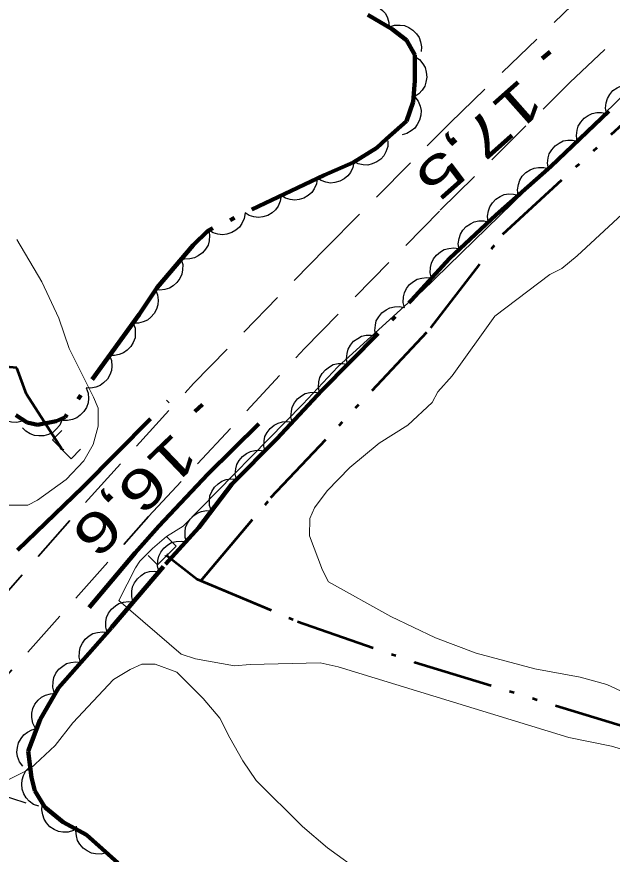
# Model space of a CAD drawing. Extents: x 386081 to 389416, y 5130568 to 5134082.
# Drawn here: x 387889.6 to 387934.2, y 5132287.6 to 5132350.3 of the extents above; entities that cross this region are included whole.
import ezdxf

# ---------------------------------------------------------------- set-up
doc = ezdxf.new("R2010")
doc.units = 0
doc.header["$LTSCALE"] = 1.2
for name, pattern in [('DASH_DOUBLE_DOT', [9.2, 5, -1.2, 0.3, -1.2, 0.3, -1.2]), ('DOT_DASHED', [7.7, 5, -1.2, 0.3, -1.2]), ('LONG_DASHED', [7.5, 6, -1.5]), ('MEDIUM_DASHED', [4.5, 3, -1.5])]:
    doc.linetypes.add(name, pattern=pattern)
for name, color, linetype, lineweight in [('2', 7, 'Continuous', 13), ('21', 7, 'LONG_DASHED', 35), ('26', 7, 'Continuous', 35), ('3', 7, 'Continuous', 140), ('4', 7, 'DASH_DOUBLE_DOT', 53), ('41', 7, 'DOT_DASHED', 25), ('44', 7, 'Continuous', 25)]:
    doc.layers.add(name, color=color, linetype=linetype, lineweight=lineweight)

msp = doc.modelspace()

# ---------------------------------------------------------------- linework, layer by layer
at = {"layer": '2'}
for points in [[(387940.27, 5132349.55), (387919.93, 5132329.72), (387918.88, 5132328.86), (387913.6, 5132324.05), (387910.99, 5132321.25), (387902.03, 5132312.13), (387900.78, 5132311.34), (387899.72, 5132310.46), (387898.77, 5132309.51), (387898.45, 5132309.01), (387897.22, 5132306.55), (387901.87, 5132302.54), (387902.94, 5132302.2), (387905.86, 5132301.67), (387907.04, 5132301.76), (387912.28, 5132301.88), (387913.63, 5132301.59), (387930.91, 5132296.29), (387934.1, 5132295.66), (387937.25, 5132294.71)], [(387887.86, 5132313.7), (387890.4, 5132313.69), (387891.11, 5132314.07), (387893.27, 5132315.62), (387894.6, 5132317.01), (387895.29, 5132318.23), (387895.67, 5132319.61), (387895.66, 5132320.97), (387895.32, 5132321.79), (387893.48, 5132325.44), (387892.71, 5132327.71), (387891.45, 5132330.42), (387889.56, 5132333.59)], [(387940, 5132297.37), (387933.76, 5132300.26), (387931.75, 5132300.82), (387928.36, 5132301.44), (387923.97, 5132302.62), (387920.93, 5132303.75), (387917.58, 5132305.37), (387912.9, 5132307.96), (387912.45, 5132308.82), (387911.48, 5132311.4), (387911.5, 5132312.7), (387911.86, 5132313.5), (387912.8, 5132314.76), (387914.5, 5132316.51), (387916.69, 5132318.33), (387918.84, 5132319.7), (387920.66, 5132321.38), (387921.1, 5132322.19), (387922.17, 5132323.38), (387925.36, 5132327.84)], [(387880.43, 5132289.92), (387882.86, 5132290.75), (387884.73, 5132291.27), (387886.72, 5132292.04), (387890.58, 5132293.94), (387892.45, 5132295.7), (387893.76, 5132297.39), (387896.81, 5132300.64), (387898.06, 5132301.4), (387898.93, 5132301.78), (387899.92, 5132301.79), (387901.54, 5132301.19)]]:
    msp.add_lwpolyline(points, dxfattribs=at)
at = {"layer": '2', "linetype": 'LONG_DASHED'}
for points in [[(387925.36, 5132327.84), (387929.48, 5132330.96), (387930.37, 5132331.43), (387931.52, 5132332.38), (387935.89, 5132336.43)], [(387901.54, 5132301.19), (387903.53, 5132299.23), (387904.77, 5132297.75), (387905.51, 5132296.27), (387906.5, 5132294.54), (387907.5, 5132293.07), (387910.97, 5132289.63), (387912.83, 5132288.04), (387919.29, 5132283.39)]]:
    msp.add_lwpolyline(points, dxfattribs=at)
at = {"layer": '21', "linetype": 'MEDIUM_DASHED'}
for points in [[(387860.78, 5132286.44), (387862.78, 5132287.28), (387865.84, 5132288.2), (387868.86, 5132289.23), (387870.95, 5132290.29), (387873.09, 5132291.74), (387875.38, 5132293.66), (387881.62, 5132300.01), (387887.6, 5132305.78), (387894.9, 5132314.12), (387902.8, 5132322.8), (387912.7, 5132332.94), (387922.03, 5132342.34), (387944.62, 5132364.16), (387960.02, 5132379.36), (387967.89, 5132387.55), (387974.37, 5132394.99), (387979.87, 5132401.66), (387990.47, 5132414.87), (387993.62, 5132418.08), (388000.82, 5132427.01), (388006.82, 5132435.09), (388017.51, 5132449)], [(387871.99, 5132283.29), (387872.81, 5132284.42), (387877.34, 5132288.8), (387880.16, 5132291.8), (387883.3, 5132295.45), (387886.81, 5132298.67), (387899.44, 5132312.84), (387911.12, 5132325.44), (387921.28, 5132335.78), (387930.99, 5132345.34), (387944.01, 5132357.8), (387957.3, 5132370.29), (387966.89, 5132380.09), (387975.16, 5132389.32), (387982.37, 5132397.55), (387987.94, 5132404.97), (387994.4, 5132413.8), (388000.29, 5132420), (388012.45, 5132436.38), (388020.46, 5132446.74)]]:
    msp.add_lwpolyline(points, dxfattribs=at)
at = {"layer": '21', "lineweight": 140}
for points in [[(387889.61, 5132310.34), (387894.52, 5132315.05), (387900.91, 5132321.49)], [(387907.68, 5132319.79), (387903.88, 5132316.01), (387900.21, 5132312.12), (387898.43, 5132310.13), (387894.99, 5132306.03)]]:
    msp.add_lwpolyline(points, dxfattribs=at)
at = {"layer": '26'}
for p, q in [((387892.24, 5132318.58), (387892.94, 5132319.28)), ((387893.64, 5132317.18), (387892.24, 5132318.58)), ((387892.87, 5132317.95), (387892.94, 5132318.02)), ((387893.01, 5132317.81), (387892.87, 5132317.95)), ((387893.01, 5132317.81), (387893.08, 5132317.88)), ((387893.64, 5132317.18), (387894.34, 5132317.88)), ((387901.5, 5132310.62), (387900.8, 5132311.32)), ((387901.5, 5132310.62), (387900.1, 5132309.22)), ((387900.1, 5132309.22), (387899.4, 5132309.92)), ((387900.73, 5132309.85), (387900.66, 5132309.92)), ((387900.87, 5132309.99), (387900.73, 5132309.85)), ((387900.87, 5132309.99), (387900.8, 5132310.06))]:
    msp.add_line(p, q, dxfattribs=at)
at = {"layer": '3'}
for p, q in [((387929.5, 5132347.66), (387928.9, 5132347.14)), ((387903.48, 5132321.24), (387902.9, 5132320.7))]:
    msp.add_line(p, q, dxfattribs=at)
at = {"layer": '4'}
for points in [[(387903.36, 5132308.04), (387908.6, 5132314.26), (387920.58, 5132326.98), (387925.96, 5132333.99), (387955.31, 5132360.98), (387968.85, 5132373.63), (387980.92, 5132386.88), (387997.63, 5132406.11), (388003.3, 5132412.46), (388006.68, 5132415.63), (388007.94, 5132417.55), (388009.44, 5132419.16), (388010.05, 5132419.23), (388010.81, 5132419.74), (388011.93, 5132420.94), (388013.08, 5132422.61), (388014.26, 5132424.98), (388016.25, 5132428.18), (388017.26, 5132429.13), (388018.5, 5132429.83), (388020.36, 5132432)], [(387892.94, 5132317.88), (387890.3, 5132322.01), (387889.56, 5132323.99), (387883.42, 5132324.53), (387868.69, 5132324.8), (387854.75, 5132324.8), (387843.78, 5132324.98), (387834.49, 5132324.37), (387825.45, 5132322.4), (387815.47, 5132320.9), (387809.16, 5132320.4), (387801.96, 5132320.97), (387796.86, 5132320.98), (387791.59, 5132322.3), (387785.98, 5132323.55), (387774.67, 5132327.23), (387758.88, 5132331.38)], [(387900.8, 5132309.92), (387903.08, 5132308.16), (387910.59, 5132304.99), (387919.35, 5132301.95), (387939.96, 5132295.61), (387941.2, 5132294.34), (387941.56, 5132292.55), (387938.27, 5132281.68), (387937.1, 5132271.81), (387937.03, 5132266.91), (387937.28, 5132262.82), (387937.15, 5132259.34), (387936.71, 5132255.8), (387935.77, 5132251.89), (387934.71, 5132248.09), (387931.98, 5132243.59), (387930.17, 5132241.03), (387926.32, 5132237.16)]]:
    msp.add_lwpolyline(points, dxfattribs=at)
at = {"layer": '41'}
msp.add_lwpolyline([(387890.27, 5132291.38), (387887.33, 5132292.33), (387886.21, 5132292.69), (387884.02, 5132293.9)], dxfattribs=at)
at = {"layer": '44'}
for points in [[(387914.87, 5132351.01), (387915.24, 5132351.19), (387915.65, 5132351.25), (387915.98, 5132351.25), (387916.32, 5132351.15), (387916.65, 5132350.99), (387916.94, 5132350.75), (387917.17, 5132350.51), (387917.32, 5132350.2), (387917.43, 5132349.84), (387917.45, 5132349.48)], [(387917.47, 5132349.51), (387917.86, 5132349.64), (387918.27, 5132349.65), (387918.6, 5132349.61), (387918.92, 5132349.48), (387919.23, 5132349.28), (387919.49, 5132348.99), (387919.69, 5132348.73), (387919.8, 5132348.4), (387919.86, 5132348.03), (387919.84, 5132347.68)], [(387919.37, 5132347.3), (387919.72, 5132347.07), (387919.97, 5132346.75), (387920.14, 5132346.47), (387920.23, 5132346.13), (387920.27, 5132345.76), (387920.2, 5132345.38), (387920.11, 5132345.07), (387919.92, 5132344.78), (387919.67, 5132344.5), (387919.37, 5132344.3)], [(387933.72, 5132343.03), (387933.65, 5132343.44), (387933.7, 5132343.84), (387933.79, 5132344.16), (387933.97, 5132344.46), (387934.21, 5132344.74), (387934.53, 5132344.95), (387934.82, 5132345.1), (387935.17, 5132345.17), (387935.54, 5132345.17), (387935.89, 5132345.1)], [(387919.37, 5132344.29), (387919.62, 5132343.96), (387919.77, 5132343.58), (387919.84, 5132343.25), (387919.82, 5132342.9), (387919.73, 5132342.54), (387919.56, 5132342.2), (387919.37, 5132341.93), (387919.1, 5132341.72), (387918.77, 5132341.54), (387918.43, 5132341.44)], [(387931.54, 5132340.96), (387931.47, 5132341.37), (387931.53, 5132341.77), (387931.61, 5132342.09), (387931.8, 5132342.39), (387932.04, 5132342.67), (387932.36, 5132342.88), (387932.65, 5132343.04), (387932.99, 5132343.1), (387933.36, 5132343.1), (387933.72, 5132343.03)], [(387917.36, 5132340.97), (387917.35, 5132340.55), (387917.21, 5132340.17), (387917.06, 5132339.87), (387916.82, 5132339.62), (387916.52, 5132339.4), (387916.17, 5132339.26), (387915.85, 5132339.17), (387915.5, 5132339.18), (387915.14, 5132339.25), (387914.81, 5132339.4)], [(387929.37, 5132338.89), (387929.3, 5132339.3), (387929.35, 5132339.7), (387929.44, 5132340.02), (387929.62, 5132340.32), (387929.87, 5132340.6), (387930.19, 5132340.81), (387930.47, 5132340.97), (387930.82, 5132341.03), (387931.19, 5132341.03), (387931.54, 5132340.96)], [(387914.81, 5132339.39), (387914.74, 5132338.98), (387914.55, 5132338.62), (387914.36, 5132338.35), (387914.08, 5132338.13), (387913.76, 5132337.95), (387913.39, 5132337.86), (387913.06, 5132337.81), (387912.72, 5132337.88), (387912.37, 5132338), (387912.06, 5132338.19)], [(387927.12, 5132336.91), (387927.06, 5132337.32), (387927.13, 5132337.72), (387927.23, 5132338.04), (387927.42, 5132338.33), (387927.68, 5132338.6), (387928, 5132338.8), (387928.3, 5132338.94), (387928.64, 5132338.99), (387929.02, 5132338.99), (387929.36, 5132338.9)], [(387912.07, 5132338.17), (387912.01, 5132337.76), (387911.84, 5132337.39), (387911.66, 5132337.11), (387911.39, 5132336.89), (387911.07, 5132336.7), (387910.7, 5132336.59), (387910.38, 5132336.54), (387910.03, 5132336.58), (387909.68, 5132336.69), (387909.37, 5132336.88)], [(387909.37, 5132336.88), (387909.3, 5132336.46), (387909.13, 5132336.1), (387908.95, 5132335.82), (387908.68, 5132335.59), (387908.36, 5132335.4), (387908, 5132335.3), (387907.67, 5132335.24), (387907.32, 5132335.29), (387906.97, 5132335.4), (387906.66, 5132335.58)], [(387924.87, 5132334.92), (387924.82, 5132335.33), (387924.88, 5132335.73), (387924.98, 5132336.05), (387925.18, 5132336.34), (387925.43, 5132336.61), (387925.76, 5132336.81), (387926.05, 5132336.96), (387926.4, 5132337.01), (387926.77, 5132337), (387927.12, 5132336.91)], [(387906.66, 5132335.58), (387906.6, 5132335.17), (387906.42, 5132334.8), (387906.24, 5132334.52), (387905.98, 5132334.3), (387905.66, 5132334.11), (387905.29, 5132334), (387904.97, 5132333.95), (387904.62, 5132333.99), (387904.26, 5132334.1), (387903.95, 5132334.29)], [(387922.7, 5132332.85), (387922.63, 5132333.26), (387922.69, 5132333.67), (387922.78, 5132333.99), (387922.96, 5132334.28), (387923.21, 5132334.56), (387923.53, 5132334.77), (387923.82, 5132334.92), (387924.16, 5132334.98), (387924.54, 5132334.98), (387924.89, 5132334.9)], [(387903.94, 5132334.31), (387904.01, 5132333.9), (387903.97, 5132333.49), (387903.89, 5132333.17), (387903.71, 5132332.87), (387903.47, 5132332.59), (387903.15, 5132332.37), (387902.87, 5132332.21), (387902.52, 5132332.15), (387902.15, 5132332.13), (387901.8, 5132332.21)], [(387920.62, 5132330.69), (387920.52, 5132331.1), (387920.55, 5132331.5), (387920.61, 5132331.83), (387920.77, 5132332.14), (387921, 5132332.43), (387921.3, 5132332.67), (387921.58, 5132332.84), (387921.92, 5132332.93), (387922.29, 5132332.96), (387922.64, 5132332.91)], [(387901.88, 5132332.13), (387901.99, 5132331.72), (387901.98, 5132331.32), (387901.93, 5132330.99), (387901.78, 5132330.67), (387901.56, 5132330.37), (387901.27, 5132330.13), (387901, 5132329.95), (387900.66, 5132329.85), (387900.29, 5132329.81), (387899.93, 5132329.85)], [(387918.6, 5132328.48), (387918.5, 5132328.88), (387918.52, 5132329.29), (387918.59, 5132329.61), (387918.75, 5132329.92), (387918.97, 5132330.22), (387919.28, 5132330.45), (387919.55, 5132330.63), (387919.89, 5132330.71), (387920.26, 5132330.74), (387920.62, 5132330.69)], [(387899.95, 5132329.83), (387900.11, 5132329.45), (387900.15, 5132329.04), (387900.14, 5132328.71), (387900.03, 5132328.38), (387899.86, 5132328.05), (387899.6, 5132327.77), (387899.35, 5132327.56), (387899.03, 5132327.42), (387898.67, 5132327.33), (387898.31, 5132327.32)], [(387916.46, 5132326.37), (387916.38, 5132326.78), (387916.42, 5132327.19), (387916.49, 5132327.51), (387916.67, 5132327.81), (387916.91, 5132328.09), (387917.22, 5132328.32), (387917.5, 5132328.48), (387917.85, 5132328.55), (387918.22, 5132328.57), (387918.57, 5132328.5)], [(387898.28, 5132327.34), (387898.42, 5132326.95), (387898.44, 5132326.55), (387898.42, 5132326.22), (387898.29, 5132325.89), (387898.1, 5132325.57), (387897.83, 5132325.3), (387897.57, 5132325.1), (387897.24, 5132324.97), (387896.88, 5132324.9), (387896.52, 5132324.91)], [(387914.34, 5132324.24), (387914.26, 5132324.65), (387914.3, 5132325.06), (387914.38, 5132325.38), (387914.56, 5132325.68), (387914.79, 5132325.97), (387915.1, 5132326.19), (387915.39, 5132326.35), (387915.73, 5132326.42), (387916.1, 5132326.44), (387916.46, 5132326.37)], [(387896.52, 5132324.91), (387896.66, 5132324.52), (387896.69, 5132324.11), (387896.66, 5132323.78), (387896.54, 5132323.46), (387896.35, 5132323.14), (387896.07, 5132322.87), (387895.82, 5132322.67), (387895.49, 5132322.54), (387895.12, 5132322.47), (387894.76, 5132322.48)], [(387912.23, 5132322.12), (387912.15, 5132322.53), (387912.19, 5132322.93), (387912.26, 5132323.25), (387912.44, 5132323.56), (387912.68, 5132323.84), (387912.99, 5132324.06), (387913.27, 5132324.22), (387913.62, 5132324.3), (387913.99, 5132324.31), (387914.34, 5132324.24)], [(387894.76, 5132322.48), (387894.91, 5132322.09), (387894.93, 5132321.68), (387894.9, 5132321.35), (387894.78, 5132321.02), (387894.59, 5132320.71), (387894.32, 5132320.44), (387894.06, 5132320.23), (387893.73, 5132320.11), (387893.37, 5132320.04), (387893.01, 5132320.05)], [(387889.98, 5132319.98), (387889.57, 5132319.89), (387889.16, 5132319.92), (387888.84, 5132319.99), (387888.53, 5132320.16), (387888.24, 5132320.39), (387888.01, 5132320.69), (387887.84, 5132320.97), (387887.76, 5132321.31), (387887.73, 5132321.68), (387887.79, 5132322.04)], [(387910.2, 5132319.91), (387910.1, 5132320.31), (387910.13, 5132320.72), (387910.19, 5132321.04), (387910.36, 5132321.36), (387910.58, 5132321.65), (387910.89, 5132321.88), (387911.17, 5132322.05), (387911.51, 5132322.14), (387911.88, 5132322.16), (387912.23, 5132322.11)], [(387892.94, 5132320.07), (387892.78, 5132319.69), (387892.51, 5132319.38), (387892.27, 5132319.15), (387891.95, 5132319), (387891.6, 5132318.9), (387891.21, 5132318.89), (387890.89, 5132318.92), (387890.56, 5132319.05), (387890.25, 5132319.25), (387889.99, 5132319.5)], [(387908.16, 5132317.71), (387908.06, 5132318.11), (387908.09, 5132318.52), (387908.15, 5132318.84), (387908.32, 5132319.15), (387908.55, 5132319.45), (387908.85, 5132319.68), (387909.13, 5132319.85), (387909.47, 5132319.93), (387909.84, 5132319.96), (387910.2, 5132319.91)], [(387906.01, 5132315.61), (387905.93, 5132316.02), (387905.97, 5132316.43), (387906.05, 5132316.75), (387906.22, 5132317.05), (387906.46, 5132317.33), (387906.77, 5132317.56), (387907.06, 5132317.72), (387907.4, 5132317.79), (387907.77, 5132317.81), (387908.12, 5132317.74)], [(387904.14, 5132313.27), (387904.01, 5132313.67), (387904, 5132314.07), (387904.03, 5132314.4), (387904.17, 5132314.72), (387904.36, 5132315.04), (387904.65, 5132315.3), (387904.91, 5132315.49), (387905.24, 5132315.61), (387905.6, 5132315.67), (387905.96, 5132315.65)], [(387902.31, 5132310.89), (387902.18, 5132311.28), (387902.17, 5132311.69), (387902.21, 5132312.02), (387902.34, 5132312.34), (387902.54, 5132312.66), (387902.82, 5132312.92), (387903.08, 5132313.11), (387903.41, 5132313.23), (387903.78, 5132313.29), (387904.14, 5132313.27)], [(387900.21, 5132308.74), (387900.11, 5132309.15), (387900.13, 5132309.55), (387900.2, 5132309.88), (387900.36, 5132310.19), (387900.58, 5132310.48), (387900.88, 5132310.72), (387901.16, 5132310.89), (387901.5, 5132310.98), (387901.87, 5132311.01), (387902.22, 5132310.96)], [(387898.28, 5132306.44), (387898.17, 5132306.84), (387898.18, 5132307.25), (387898.23, 5132307.57), (387898.39, 5132307.89), (387898.6, 5132308.19), (387898.89, 5132308.44), (387899.16, 5132308.62), (387899.5, 5132308.72), (387899.87, 5132308.76), (387900.23, 5132308.72)], [(387896.34, 5132304.15), (387896.23, 5132304.56), (387896.24, 5132304.96), (387896.29, 5132305.29), (387896.44, 5132305.61), (387896.66, 5132305.91), (387896.95, 5132306.15), (387897.22, 5132306.34), (387897.56, 5132306.43), (387897.93, 5132306.48), (387898.28, 5132306.44)], [(387894.35, 5132301.91), (387894.24, 5132302.32), (387894.26, 5132302.72), (387894.32, 5132303.05), (387894.48, 5132303.36), (387894.7, 5132303.66), (387894.99, 5132303.9), (387895.27, 5132304.08), (387895.61, 5132304.17), (387895.98, 5132304.21), (387896.33, 5132304.16)], [(387892.36, 5132299.66), (387892.26, 5132300.07), (387892.28, 5132300.47), (387892.33, 5132300.8), (387892.49, 5132301.11), (387892.71, 5132301.41), (387893.01, 5132301.65), (387893.28, 5132301.83), (387893.62, 5132301.92), (387893.99, 5132301.96), (387894.35, 5132301.91)], [(387890.94, 5132297.01), (387890.76, 5132297.38), (387890.69, 5132297.79), (387890.69, 5132298.12), (387890.78, 5132298.46), (387890.93, 5132298.79), (387891.18, 5132299.09), (387891.41, 5132299.31), (387891.73, 5132299.47), (387892.08, 5132299.58), (387892.44, 5132299.61)], [(387890.01, 5132294.14), (387889.76, 5132294.48), (387889.63, 5132294.87), (387889.57, 5132295.19), (387889.61, 5132295.54), (387889.7, 5132295.9), (387889.9, 5132296.23), (387890.09, 5132296.49), (387890.37, 5132296.7), (387890.7, 5132296.87), (387891.05, 5132296.96)], [(387891.22, 5132291.15), (387890.83, 5132291.29), (387890.5, 5132291.54), (387890.27, 5132291.77), (387890.1, 5132292.08), (387889.98, 5132292.42), (387889.95, 5132292.81), (387889.96, 5132293.13), (387890.07, 5132293.46), (387890.25, 5132293.79), (387890.49, 5132294.06)], [(387893.81, 5132289.34), (387893.42, 5132289.22), (387893.01, 5132289.22), (387892.68, 5132289.26), (387892.36, 5132289.41), (387892.05, 5132289.62), (387891.8, 5132289.9), (387891.61, 5132290.17), (387891.51, 5132290.5), (387891.45, 5132290.87), (387891.48, 5132291.23)], [(387896.28, 5132287.67), (387895.88, 5132287.57), (387895.47, 5132287.59), (387895.15, 5132287.64), (387894.83, 5132287.8), (387894.54, 5132288.02), (387894.3, 5132288.32), (387894.12, 5132288.59), (387894.03, 5132288.93), (387893.99, 5132289.3), (387894.03, 5132289.66)]]:
    msp.add_lwpolyline(points, dxfattribs=at)
at = {"layer": '44', "linetype": 'DOT_DASHED', "lineweight": 90}
for points in [[(387915.86, 5132350.42), (387917.67, 5132349.35), (387918.76, 5132348.51), (387919.37, 5132347.42), (387919.37, 5132345.48), (387919.24, 5132343.9), (387918.76, 5132342.45), (387917.25, 5132341.12)], [(387897.14, 5132286.92), (387894.78, 5132289), (387893.04, 5132289.97), (387891.67, 5132291.08), (387890.93, 5132292.31), (387890.68, 5132293.3), (387890.43, 5132295.28), (387891.31, 5132297.65), (387892.68, 5132300.02), (387896.66, 5132304.53), (387900.7, 5132309.28), (387903.19, 5132312.03), (387905.68, 5132315.28), (387909.04, 5132318.66), (387912.4, 5132322.29), (387919.12, 5132329.05), (387921.98, 5132332.18), (387925.46, 5132335.44), (387929.56, 5132339.07), (387939.56, 5132348.59)], [(387917.25, 5132341.12), (387916.52, 5132340.45), (387914.75, 5132339.36), (387912.59, 5132338.42), (387903.88, 5132334.25), (387902.78, 5132333.17), (387900.07, 5132330.01), (387898.73, 5132327.97), (387893.19, 5132320.3), (387892.52, 5132319.99), (387891.13, 5132319.72), (387890.34, 5132319.88), (387889.49, 5132320.44)]]:
    msp.add_lwpolyline(points, dxfattribs=at)

# ---------------------------------------------------------------- texts
at = {"layer": '3', "width": 1.4}
for s, rotation, p in [('17,5   ', 221.58, (387927.32, 5132345.78)), ('16,6   ', 223.744, (387901.37, 5132319.28))]:
    msp.add_text(s, height=3, rotation=rotation, dxfattribs=at).set_placement(p)

doc.saveas('drawing.dxf')
